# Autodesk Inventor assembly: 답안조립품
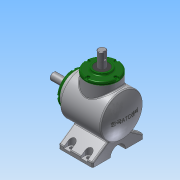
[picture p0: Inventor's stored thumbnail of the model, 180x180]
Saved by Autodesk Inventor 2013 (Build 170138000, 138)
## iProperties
Created: 2017-04
Part Number: 답안조립품
Document SubType Name: Assembly
Designer: Administrator
Author: Administrator
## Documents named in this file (13)
- C:\Users\Administrator\Desktop\470407V1007\답안조립품.iam
- C:\Users\Administrator\Desktop\470407V1007\본체.ipt
- C:\Users\Administrator\Desktop\470407V1007\커버.ipt
- C:\Users\Administrator\Desktop\470407V1007\메인 축.ipt
- 메인 축.ipt
- C:\Users\Administrator\Desktop\470407V1007\메인 베벨기어.ipt
- C:\Users\Administrator\Desktop\470407V1007\키 5x5.ipt
- C:\Users\Administrator\Desktop\470407V1007\베어링 6203.ipt
- C:\Users\Administrator\Desktop\470407V1007\서브 축.ipt
- 서브 축.ipt
- C:\Users\Administrator\Desktop\470407V1007\서브 베벨기어.ipt
- C:\Users\Administrator\Desktop\470407V1007\오일실 17 32 8.ipt
- C:\Users\Administrator\Desktop\470407V1007\키 4x4.ipt
